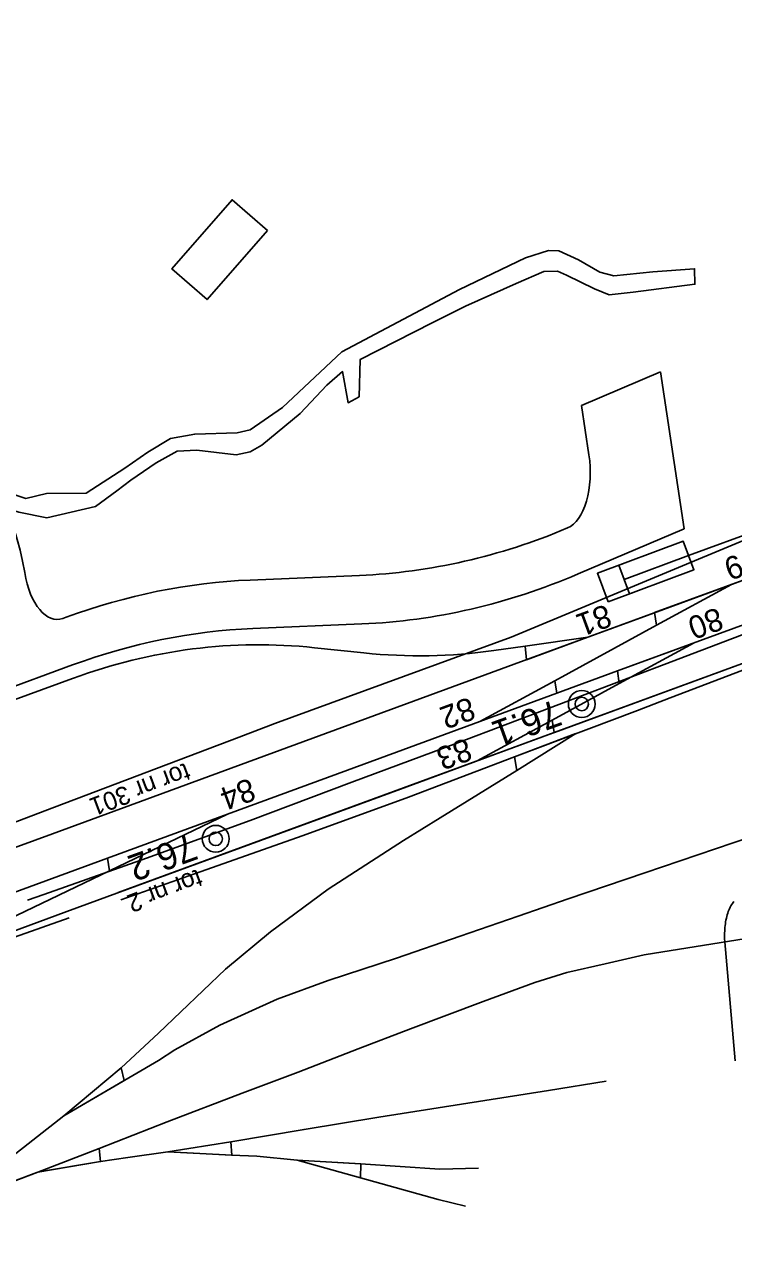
# Model space of a CAD drawing. Extents: x 6541740 to 6566395, y 5525066 to 5530361.
# Drawn here: x 6553711.2 to 6553757.6, y 5525255.7 to 5525336.7 of the extents above; entities that cross this region are included whole.
import ezdxf

# ---------------------------------------------------------------- set-up
doc = ezdxf.new("R2010")
doc.units = 0
for name, color, linetype in [('Domyślna', 7, 'Continuous'), ('ps_wymiarowanie', 7, 'Continuous'), ('TOR_PRZEK_P-komponent', 7, 'Continuous'), ('TOR_PS_OPIS_O-opisy odwodnienia', 7, 'Continuous'), ('TOR_PS_OPIS_T-symbole geometrii', 7, 'Continuous'), ('TOR_PS_OPIS_T-ukresy', 7, 'Continuous'), ('TOR_PS_T-rowy otwarte nieumocnione', 7, 'Continuous'), ('TOR_PS_T-wypelnienia', 7, 'Continuous'), ('TOR_RAMKI-ramka+tabelka 1', 7, 'Continuous')]:
    doc.layers.add(name, color=color, linetype=linetype)

# ---------------------------------------------------------------- blocks, each defined once
blk = doc.blocks.new('4010_1')
at = {"layer": 'Domyślna'}
for radius in [0.75, 0.375]:
    blk.add_circle((0, 0), radius, dxfattribs=at)
blk = doc.blocks.new('koziol 15+5')
at = {"layer": 'Domyślna'}
for p, q in [((15, 1), (14.3, 1)), ((15, 1), (15, -1)), ((20, 0), (20, 1)), ((0, 0), (15, 0)), ((15, -1), (14.3, -1))]:
    blk.add_line(p, q, dxfattribs=at)
blk.add_lwpolyline([(20, 1), (0, 1), (0, -1), (20, -1)], close=True, dxfattribs=at)

msp = doc.modelspace()

# ---------------------------------------------------------------- linework, layer by layer
at = {"layer": 'ps_wymiarowanie'}
msp.add_lwpolyline([(6553727.091, 5525323.178), (6553723.144, 5525318.641), (6553720.834, 5525320.65), (6553724.78, 5525325.187)], close=True, dxfattribs=at)
at = {"layer": 'TOR_PRZEK_P-komponent'}
for p, q in [((6553872.362, 5525336.67), (6553717.321, 5525279.728)), ((6553872.362, 5525336.67), (6553717.321, 5525279.728)), ((6553872.362, 5525336.67), (6553717.321, 5525279.728)), ((6553829.703, 5525321.003), (6553717.321, 5525279.728)), ((6553800.253, 5525310.187), (6553745.901, 5525290.225)), ((6553800.253, 5525310.187), (6553745.922, 5525290.233)), ((6553763.778, 5525305.176), (6553754.704, 5525301.844)), ((6553763.782, 5525302.248), (6553745.413, 5525295.501)), ((6553763.782, 5525302.248), (6553751.995, 5525297.919)), ((6553763.782, 5525302.248), (6553753.693, 5525298.543)), ((6553762.569, 5525301.802), (6553752.48, 5525298.097)), ((6553773.675, 5525300.426), (6553717.321, 5525279.728)), ((6553752.48, 5525298.097), (6553757.525, 5525299.95)), ((6553751.995, 5525297.919), (6553745.413, 5525295.501)), ((6553760.127, 5525297.975), (6553750.038, 5525294.27)), ((6553753.693, 5525298.543), (6553751.995, 5525297.919)), ((6553745.934, 5525293.635), (6553752.61, 5525297.272)), ((6553750.661, 5525297.429), (6553748.109, 5525296.492)), ((6553743.984, 5525295.904), (6553748.109, 5525296.492)), ((6553748.109, 5525296.492), (6553744.079, 5525295.011)), ((6553745.413, 5525295.501), (6553713.002, 5525283.598)), ((6553733.419, 5525295.459), (6553730.19, 5525295.799)), ((6553743.984, 5525295.904), (6553741.941, 5525295.612)), ((6553744.079, 5525295.011), (6553743.984, 5525295.904)), ((6553750.038, 5525294.27), (6553755.082, 5525296.122)), ((6553714.328, 5525293.784), (6553707.182, 5525291.16)), ((6553750.038, 5525294.27), (6553746.064, 5525292.81)), ((6553745.772, 5525291.05), (6553750.167, 5525293.445)), ((6553746.064, 5525292.81), (6553735.975, 5525289.105)), ((6553746.064, 5525292.81), (6553741.019, 5525290.958)), ((6553745.901, 5525290.225), (6553735.812, 5525286.52)), ((6553745.901, 5525290.225), (6553740.857, 5525288.372)), ((6553735.975, 5525289.105), (6553732.336, 5525287.769)), ((6553732.336, 5525287.769), (6553716.614, 5525281.995)), ((6553735.812, 5525286.52), (6553713.956, 5525278.492)), ((6553724.475, 5525284.882), (6553716.614, 5525281.995)), ((6553713.002, 5525283.598), (6553696.886, 5525277.679)), ((6553716.614, 5525281.995), (6553707.864, 5525278.781)), ((6553716.739, 5525281.157), (6553710.099, 5525277.96)), ((6553713.956, 5525278.492), (6553710.224, 5525277.122))]:
    msp.add_line(p, q, dxfattribs=at)
for points in [[(6553757.525, 5525299.95), (6553752.61, 5525297.272), (6553752.48, 5525298.097)], [(6553743.984, 5525295.904), (6553744.079, 5525295.011), (6553748.109, 5525296.492), (6553743.984, 5525295.904)], [(6553755.082, 5525296.122), (6553750.167, 5525293.445), (6553750.038, 5525294.27)], [(6553741.019, 5525290.958), (6553745.934, 5525293.635), (6553746.064, 5525292.81)], [(6553740.857, 5525288.372), (6553745.772, 5525291.05), (6553745.901, 5525290.225)], [(6553716.614, 5525281.995), (6553716.739, 5525281.157), (6553724.475, 5525284.882)]]:
    msp.add_lwpolyline(points, dxfattribs=at)
for centre, start_param, end_param in [((6553731.836, 5525163.819), 6.201573, 6.438521), ((6553731.772, 5525427.438), 3.059981, 3.186271)]:
    msp.add_ellipse(centre, major_axis=(-7.166, 132.121), ratio=0.510219, start_param=start_param, end_param=end_param, dxfattribs=at)
at = {"layer": 'TOR_PS_OPIS_T-symbole geometrii'}
for p, q in [((6553752.865, 5525313.892), (6553747.692, 5525311.682)), ((6553754.408, 5525303.602), (6553752.865, 5525313.892)), ((6553748.176, 5525308.452), (6553747.692, 5525311.682)), ((6553754.408, 5525303.602), (6553747.462, 5525300.634)), ((6553733.133, 5525300.541), (6553725.973, 5525300.238)), ((6553713.898, 5525297.794), (6553713.685, 5525297.716)), ((6553733.296, 5525297.36), (6553726.136, 5525297.057)), ((6553714.32, 5525294.665), (6553707.464, 5525292.147))]:
    msp.add_line(p, q, dxfattribs=at)
for centre, major_axis, start_param, end_param in [((6553705.642, 5525298), (-0.617, 11.377), 4.926158, 5.998427), ((6553746.191, 5525307.604), (0.219, -4.037), 0.180818, 1.754669), ((6553725.706, 5525445.773), (7.876, -145.211), 6.277136, 6.464004), ((6553713.15, 5525301.687), (-0.219, 4.037), 1.784565, 3.296928), ((6553733.563, 5525151.825), (-8.048, 148.391), 6.277136, 6.438521), ((6553725.706, 5525445.773), (8.048, -148.391), 6.277136, 6.467058), ((6553733.563, 5525151.825), (-7.876, 145.211), 6.277136, 6.438521)]:
    msp.add_ellipse(centre, major_axis=major_axis, ratio=0.510219, start_param=start_param, end_param=end_param, dxfattribs=at)
at = {"layer": 'TOR_PS_OPIS_T-ukresy'}
for points in [[(6553727.593, 5525290.823), (6553725.244, 5525289.932), (6553713.147, 5525285.334), (6553701.018, 5525280.733)], [(6553709.473, 5525260.428), (6553711.981, 5525261.373)], [(6553712.103, 5525261.406), (6553716.154, 5525262.09)]]:
    msp.add_lwpolyline(points, dxfattribs=at)
at = {"layer": 'TOR_PS_T-rowy otwarte nieumocnione'}
for points in [[(6553717.491, 5525279.265), (6553722.324, 5525280.959), (6553729.45, 5525283.485), (6553736.346, 5525285.992), (6553743.298, 5525288.641), (6553751.353, 5525291.684), (6553753.508, 5525292.502), (6553760.565, 5525295.193), (6553768.602, 5525298.255), (6553780.473, 5525302.767), (6553787.423, 5525305.388), (6553794.395, 5525308.012), (6553801.209, 5525310.59), (6553807.288, 5525312.878), (6553820.952, 5525318.032), (6553827.584, 5525320.508), (6553829.995, 5525321.368), (6553832.415, 5525322.202), (6553834.746, 5525322.989), (6553840.952, 5525324.967)], [(6553727.593, 5525290.823), (6553743.085, 5525296.486), (6553758.35, 5525302.859), (6553763.794, 5525305.132)], [(6553711.365, 5525279.226), (6553712.437, 5525279.604), (6553719.169, 5525282.001), (6553725.975, 5525284.472), (6553732.638, 5525286.98), (6553739.509, 5525289.539), (6553746.2, 5525292.062), (6553753.115, 5525294.689), (6553760.049, 5525297.336)], [(6553701.018, 5525280.733), (6553713.147, 5525285.334), (6553725.244, 5525289.932), (6553727.593, 5525290.823)], [(6553747.323, 5525290.162), (6553743.456, 5525287.744), (6553738.422, 5525284.638), (6553736.013, 5525283.141), (6553731.077, 5525279.962), (6553727.302, 5525277.154), (6553724.35, 5525274.701), (6553719.958, 5525270.5), (6553717.51, 5525268.234), (6553713.756, 5525265.092)], [(6553713.756, 5525265.092), (6553719.957, 5525268.712), (6553721.018, 5525269.415), (6553723.976, 5525271.033), (6553727.742, 5525272.75), (6553731.086, 5525273.97), (6553735.556, 5525275.435), (6553739.732, 5525276.881), (6553743.534, 5525278.179), (6553746.813, 5525279.326), (6553751.84, 5525281.018), (6553757.64, 5525283.001), (6553761.46, 5525284.284), (6553769.95, 5525287.109), (6553772.356, 5525287.857)], [(6553713.756, 5525265.092), (6553719.957, 5525268.712), (6553721.018, 5525269.415), (6553723.976, 5525271.033), (6553727.742, 5525272.75), (6553731.086, 5525273.97), (6553735.556, 5525275.435), (6553739.732, 5525276.881), (6553743.534, 5525278.179), (6553746.813, 5525279.326), (6553751.84, 5525281.018), (6553757.64, 5525283.001), (6553761.46, 5525284.284), (6553769.95, 5525287.109), (6553772.356, 5525287.857)], [(6553687.683, 5525251.946), (6553708.038, 5525259.886), (6553712.041, 5525261.396), (6553716.068, 5525262.95), (6553720.534, 5525264.692), (6553725.448, 5525266.581), (6553729.114, 5525267.952), (6553733.04, 5525269.484), (6553736.472, 5525270.789), (6553741.248, 5525272.578), (6553744.632, 5525273.83), (6553746.73, 5525274.488), (6553749.248, 5525275.068), (6553751.804, 5525275.655), (6553759.026, 5525276.811), (6553763.436, 5525277.444), (6553766.319, 5525277.902), (6553770.764, 5525278.618), (6553773.744, 5525279.084), (6553777.062, 5525279.624), (6553780.457, 5525280.104), (6553784.043, 5525280.753)], [(6553651.731, 5525255.803), (6553682.605, 5525267.065), (6553685.309, 5525267.992), (6553692.203, 5525270.402), (6553699.024, 5525272.781), (6553700.447, 5525273.28), (6553701.115, 5525273.512), (6553708.324, 5525276.048), (6553714.108, 5525278.079)], [(6553712.041, 5525261.396), (6553716.151, 5525262.089), (6553717.952, 5525262.349), (6553720.575, 5525262.732), (6553724.694, 5525263.38), (6553729.499, 5525264.195), (6553734.408, 5525265.001), (6553739.827, 5525265.861), (6553745.53, 5525266.751), (6553749.308, 5525267.359)], [(6553713.756, 5525265.092), (6553709.995, 5525262.142), (6553707.882, 5525260.732), (6553704.035, 5525258.325), (6553704.035, 5525258.325), (6553704.035, 5525258.325)], [(6553720.575, 5525262.732), (6553724.737, 5525262.504), (6553726.41, 5525262.439), (6553729.043, 5525262.179), (6553733.193, 5525261.939), (6553738.389, 5525261.595), (6553740.929, 5525261.65)], [(6553729.043, 5525262.179), (6553733.198, 5525261.03), (6553738.295, 5525259.594), (6553740.092, 5525259.151)]]:
    msp.add_lwpolyline(points, dxfattribs=at)
for points in [[(6553747.323, 5525290.162), (6553743.298, 5525288.641), (6553743.456, 5525287.744)], [(6553713.756, 5525265.092), (6553717.51, 5525268.234), (6553717.707, 5525267.398)], [(6553712.041, 5525261.396), (6553716.068, 5525262.95), (6553716.158, 5525262.09)], [(6553720.575, 5525262.732), (6553724.694, 5525263.38), (6553724.762, 5525262.503)], [(6553729.043, 5525262.179), (6553733.216, 5525261.938), (6553733.201, 5525261.029)]]:
    msp.add_lwpolyline(points, close=True, dxfattribs=at)
at = {"layer": 'TOR_PS_T-wypelnienia'}
for points in [[(6553710.605, 5525305.798), (6553711.254, 5525305.578), (6553712.619, 5525305.921), (6553715.218, 5525305.933), (6553717.738, 5525307.586), (6553719.252, 5525308.623), (6553720.736, 5525309.512), (6553722.333, 5525309.812), (6553725.117, 5525309.899), (6553725.963, 5525310.083), (6553728.081, 5525311.547), (6553731.964, 5525315.213), (6553739.685, 5525319.305), (6553744.027, 5525321.385), (6553745.52, 5525321.867), (6553746.207, 5525321.842), (6553747.492, 5525321.253), (6553748.893, 5525320.427), (6553749.817, 5525320.188), (6553752.37, 5525320.462), (6553755.106, 5525320.659), (6553755.125, 5525319.637), (6553751.074, 5525319.117), (6553749.494, 5525318.956), (6553748.54, 5525319.333), (6553746.71, 5525320.238), (6553746.106, 5525320.497), (6553745.21, 5525320.469), (6553743.395, 5525319.681), (6553740.085, 5525318.203), (6553737.896, 5525317.102), (6553733.186, 5525314.715), (6553733.101, 5525312.251)], [(6553733.101, 5525312.251), (6553732.385, 5525311.872), (6553732.019, 5525313.915), (6553730.987, 5525313.026), (6553729.243, 5525311.158), (6553726.72, 5525309.089), (6553725.962, 5525308.649), (6553725.054, 5525308.454), (6553722.469, 5525308.761), (6553721.187, 5525308.684), (6553719.801, 5525307.928), (6553718.136, 5525306.784), (6553717.229, 5525306.08), (6553715.823, 5525305.055), (6553712.626, 5525304.322), (6553710.806, 5525304.68), (6553709.877, 5525304.979), (6553705.829, 5525306.556)], [(6553757.682, 5525279.149), (6553757.63, 5525279.083), (6553757.579, 5525279.012), (6553757.53, 5525278.936), (6553757.483, 5525278.854), (6553757.437, 5525278.768), (6553757.394, 5525278.677), (6553757.353, 5525278.581), (6553757.314, 5525278.482), (6553757.278, 5525278.378), (6553757.244, 5525278.271), (6553757.213, 5525278.16), (6553757.185, 5525278.047), (6553757.16, 5525277.931), (6553757.138, 5525277.813), (6553757.119, 5525277.693), (6553757.104, 5525277.573), (6553757.091, 5525277.451), (6553757.081, 5525277.329), (6553757.074, 5525277.207), (6553757.069, 5525277.085), (6553757.068, 5525276.964), (6553757.069, 5525276.844), (6553757.073, 5525276.726), (6553757.088, 5525276.494), (6553757.766, 5525268.704)]]:
    msp.add_lwpolyline(points, dxfattribs=at)

# ---------------------------------------------------------------- block references
at = {"layer": 'TOR_PRZEK_P-komponent', "xscale": 0.2999999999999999, "rotation": -159.5035582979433}
msp.add_blockref('koziol 15+5', (6553754.704, 5525301.844), dxfattribs=at)
at = {"layer": 'TOR_RAMKI-ramka+tabelka 1', "xscale": 1.175388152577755, "yscale": 1.1753881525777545, "rotation": -7.7666346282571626}
for p in [(6553747.706, 5525292.103), (6553723.708, 5525283.26)]:
    msp.add_blockref('4010_1', p, dxfattribs=at)

# ---------------------------------------------------------------- texts
at = {"layer": 'TOR_PS_OPIS_O-opisy odwodnienia'}
for s, height, rotation, p in [('79', 1.5, 200.1668, (6553758.995, 5525302.353)), ('81', 1.5, 200.1668, (6553749.303, 5525298.68)), ('80', 1.5, 200.1668, (6553756.623, 5525298.476)), ('82', 1.5, 200.1668, (6553740.365, 5525292.592)), ('83', 1.5, 200.1668, (6553740.145, 5525289.906)), ('tor nr 301', 1.2, 200.65486, (6553721.75, 5525288.273)), ('84', 1.5, 200.1668, (6553725.953, 5525287.275)), ('tor nr 2', 1.2, 200.65486, (6553722.539, 5525281.3))]:
    msp.add_text(s, height=height, rotation=rotation, dxfattribs=at).set_placement(p)
at = {"layer": 'TOR_RAMKI-ramka+tabelka 1'}
for s, p in [('76.1', (6553745.943, 5525292.419)), ('76.2', (6553722.071, 5525283.621))]:
    msp.add_text(s, height=1.7465, rotation=199.90521, dxfattribs=at).set_placement(p)

doc.saveas('drawing.dxf')
